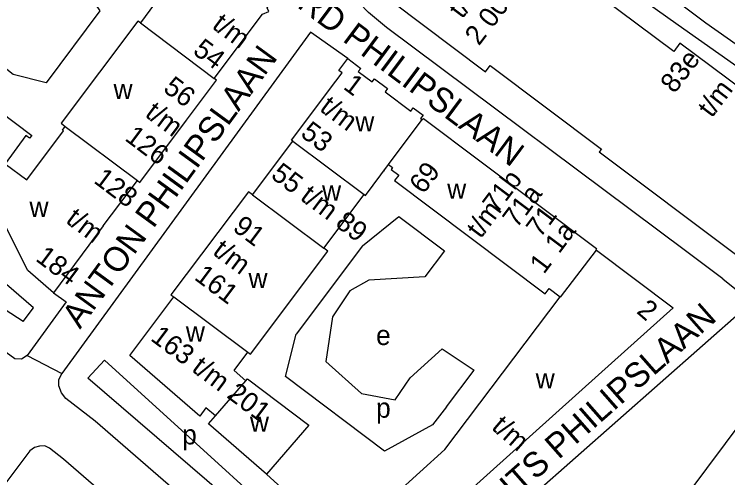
# Model space of a CAD drawing. Extents: x 159261 to 160849, y 382514 to 384534.
# Drawn here: x 160354.6 to 160499.4, y 383689.7 to 383783.7 of the extents above; entities that cross this region are included whole.
import ezdxf

# ---------------------------------------------------------------- set-up
doc = ezdxf.new("R2010")
doc.units = 0
for name, color, linetype in [('BLT_Basislijn', 7, 'Continuous'), ('BLT_Bebouwing', 7, 'Continuous'), ('BLT_Centroide', 7, 'Continuous'), ('BLT_Huisnummer_reeks', 7, 'Continuous'), ('BLT_Huisnummer_zonder_bebouwing', 7, 'Continuous'), ('BLT_Onderverdeling_panden', 7, 'Continuous'), ('BLT_Plantopo', 7, 'Continuous'), ('BLT_Straatnaam', 7, 'Continuous'), ('BLT_Vlakafsluiter', 7, 'Continuous')]:
    doc.layers.add(name, color=color, linetype=linetype)

msp = doc.modelspace()

# ---------------------------------------------------------------- linework, layer by layer
at = {"layer": 'BLT_Basislijn'}
for p, q in [((160490.83, 383735.75), (160430.14, 383781.07)), ((160414.75, 383780.08), (160364.27, 383710.87)), ((160422.31, 383774.74), (160414.75, 383780.08)), ((160425.28, 383736.74), (160411.83, 383718.83)), ((160498.4, 383730.1), (160490.83, 383735.75)), ((160498.4, 383730.1), (160504.24, 383725.34)), ((160452.04, 383679.36), (160504.24, 383725.34)), ((160409.64, 383710.25), (160411.83, 383718.83)), ((160442.32, 383704.12), (160447.92, 383711.55)), ((160429.75, 383695.14), (160409.64, 383710.25)), ((160405.79, 383690.47), (160421.08, 383676.58))]:
    msp.add_line(p, q, dxfattribs=at)
for points in [[(160452.11, 383810.43), (160463.68, 383799.88), (160489.37, 383781.57), (160512.99, 383764.97)], [(160544.3, 383749.08), (160528.34, 383759.05), (160510.47, 383771.01), (160494.97, 383781.94), (160478.14, 383794.64)], [(160430.14, 383781.07), (160426.48, 383784.08), (160424.69, 383785.96), (160423.59, 383788.37)], [(160356.44, 383721.41), (160325.99, 383741.08), (160322.06, 383744.73), (160318.31, 383749.67), (160315.16, 383755.44), (160313.52, 383760.62), (160312.98, 383767.15), (160313.74, 383774.42)], [(160357.23, 383714.5), (160356.07, 383713.77), (160354.74, 383713.87), (160333.91, 383729), (160312.13, 383743.88), (160309.97, 383745.04)], [(160425.28, 383736.74), (160432.69, 383742.73), (160441.94, 383735.73), (160437.95, 383730.45), (160426.59, 383729.78), (160422.7, 383727.62), (160419.17, 383722.34), (160417.83, 383713.29), (160425.11, 383706.82), (160431.92, 383705.5), (160434.96, 383709.97), (160441.48, 383715.86), (160447.92, 383711.55)], [(160356.44, 383721.41), (160358.5, 383724.16), (160351.51, 383730.21)], [(160362.56, 383727.26), (160365.14, 383725.38), (160357.23, 383714.5)], [(160369.56, 383709.91), (160372.9, 383713.59), (160424.43, 383666.77)], [(160422.06, 383664.61), (160418.47, 383660.86), (160417.7, 383660.66), (160416.97, 383660.91), (160410.42, 383667.03), (160371, 383701.19), (160365.08, 383705.81), (160364.23, 383706.97), (160363.68, 383708.34), (160363.68, 383709.56), (160364.27, 383710.87)], [(160422.06, 383664.61), (160421.23, 383665.48), (160369.56, 383709.91)], [(160442.32, 383704.12), (160439.46, 383700.46), (160429.75, 383695.14)], [(160406.32, 383652.42), (160407.01, 383653.62), (160407.25, 383654.84), (160406.99, 383656.12), (160406.32, 383657.17), (160403.73, 383659.59), (160364.64, 383693.46), (160361.79, 383695.69), (160360.82, 383696.18), (160359.71, 383696.14), (160358.73, 383695.85), (160357.8, 383695.17), (160352.3, 383687.91)]]:
    msp.add_lwpolyline(points, dxfattribs=at)
msp.add_lwpolyline([(160343.33, 383806.99), (160355.95, 383800.68), (160367.21, 383791.56), (160371.98, 383784.4), (160361.11, 383769.8), (160354.39, 383771.52), (160352.8, 383772.83), (160335.58, 383799.67)], close=True, dxfattribs=at)
at = {"layer": 'BLT_Bebouwing'}
for p, q in [((160384.23, 383787.44), (160380.2, 383781.98)), ((160402.94, 383747.13), (160411.13, 383758.02)), ((160372.65, 383740.8), (160379.6, 383750.02)), ((160417.43, 383736.28), (160425.65, 383747.18)), ((160472.75, 383735.87), (160488.34, 383724.17)), ((160442.02, 383695.42), (160465.41, 383726.43)), ((160513.51, 383716.32), (160478.99, 383670.1)), ((160421.08, 383676.58), (160442.02, 383695.42))]:
    msp.add_line(p, q, dxfattribs=at)
for points in [[(160395.17, 383770.72), (160404.99, 383783.76), (160406.29, 383784.32), (160405.96, 383785.06), (160406.35, 383785.58), (160400.96, 383789.62), (160401.47, 383790.32), (160399.76, 383791.6), (160399.23, 383790.9), (160393.76, 383795.02), (160394.27, 383795.73), (160392.56, 383797.01), (160392.04, 383796.31), (160391.36, 383796.81)], [(160380.2, 383781.98), (160379.69, 383782.36), (160364.16, 383761.62), (160364.97, 383760.99)], [(160411.13, 383758.02), (160410.9, 383758.2), (160415, 383763.69), (160418.62, 383768.5), (160421.15, 383771.87), (160420.51, 383772.35), (160422.31, 383774.74)], [(160422.31, 383774.74), (160424.92, 383772.75), (160424.43, 383772.1), (160427.22, 383770.01), (160427.7, 383770.66), (160430.37, 383768.66), (160429.9, 383768), (160435.08, 383764.1), (160435.58, 383764.75), (160437.57, 383763.24)], [(160380.1, 383749.63), (160389.58, 383762.26), (160395.64, 383770.34), (160395.17, 383770.72)], [(160345.09, 383768.93), (160358.15, 383759.16), (160357.71, 383758.58), (160356.99, 383759.12), (160352.74, 383753.42), (160357.14, 383750.13), (160364.58, 383760.07), (160364.38, 383760.23), (160364.97, 383760.99)], [(160362.56, 383727.26), (160357.34, 383731.78), (160339.93, 383766.34), (160339.83, 383766.29)], [(160437.57, 383763.24), (160437.08, 383762.6), (160437.41, 383762.37)], [(160437.41, 383762.37), (160437.64, 383762.61), (160472.81, 383736.19), (160472.64, 383735.95), (160472.75, 383735.87)], [(160425.65, 383747.18), (160425.88, 383747), (160430.58, 383753.24)], [(160430.58, 383753.24), (160431.4, 383752.62), (160431.12, 383752.25), (160432.63, 383751.11), (160431.81, 383749.99), (160462.35, 383727.06), (160463.15, 383728.13), (160465.41, 383726.43)], [(160429.69, 383752.08), (160429.58, 383751.93), (160429.54, 383751.96)], [(160379.6, 383750.02), (160380.1, 383749.63)], [(160402.94, 383747.13), (160402.14, 383747.73), (160386.42, 383726.84), (160386.98, 383726.4)], [(160372.65, 383740.8), (160362.56, 383727.26)], [(160401.99, 383715.21), (160402.55, 383714.79), (160418.22, 383735.67), (160417.43, 383736.28)], [(160395.43, 383702.25), (160393.51, 383703.9), (160392.25, 383702.2), (160378.05, 383714.53), (160386.98, 383726.4)], [(160488.34, 383724.17), (160473.21, 383710.61), (160441.83, 383682.45), (160428.3, 383670.3)], [(160401.63, 383709.4), (160399.21, 383711.5), (160401.99, 383715.21)], [(160401.63, 383709.4), (160401.95, 383709.77), (160414.42, 383700.41), (160405.79, 383690.47)], [(160405.79, 383690.47), (160394.04, 383700.66), (160395.43, 383702.25)]]:
    msp.add_lwpolyline(points, dxfattribs=at)
at = {"layer": 'BLT_Onderverdeling_panden'}
for p, q in [((160380.2, 383781.98), (160395.17, 383770.72)), ((160430.58, 383753.24), (160437.41, 383762.37)), ((160364.97, 383760.99), (160379.6, 383750.02)), ((160411.13, 383758.02), (160425.65, 383747.18)), ((160402.94, 383747.13), (160417.43, 383736.28)), ((160386.98, 383726.4), (160401.99, 383715.21)), ((160395.43, 383702.25), (160401.63, 383709.4))]:
    msp.add_line(p, q, dxfattribs=at)
msp.add_lwpolyline([(160465.41, 383726.43), (160465.48, 383726.37), (160472.75, 383735.87)], dxfattribs=at)
at = {"layer": 'BLT_Plantopo'}
msp.add_lwpolyline([(160447.81, 383808.7), (160431.12, 383786.45), (160450.27, 383772.09), (160451.2, 383773.33), (160473.81, 383756.36), (160473.32, 383755.83), (160501.01, 383735.05), (160522.32, 383753.63), (160489.69, 383777.86), (160488.44, 383776.16), (160465.9, 383793.07), (160466.89, 383794.39)], close=True, dxfattribs=at)
at = {"layer": 'BLT_Vlakafsluiter'}
msp.add_line((160357.23, 383714.5), (160364.27, 383710.87), dxfattribs=at)

# ---------------------------------------------------------------- texts
at = {"layer": 'BLT_Centroide'}
for s, p in [('w', (160374.76, 383766.52)), ('w', (160423.83, 383759.99)), ('w', (160417.08, 383745.94)), ('w', (160442.47, 383746.3)), ('w', (160357.7, 383742.62)), ('w', (160402.15, 383728.18)), ('w', (160389.44, 383717.33)), ('e', (160428.04, 383716.64)), ('w', (160460.44, 383707.83)), ('p', (160428.04, 383701.9)), ('w', (160402.44, 383699.04)), ('p', (160388.68, 383696.48))]:
    msp.add_text(s, height=4, dxfattribs=at).set_placement(p)
at = {"layer": 'BLT_Huisnummer_reeks'}
for s, rotation, p in [('t/m', 323.1346, (160394.54, 383781.06)), ('54', 323.1346, (160390.65, 383775.89)), ('56', 323.1346, (160384.63, 383768.25)), ('1', 323.1346, (160421.19, 383768.75)), ('t/m', 323.1346, (160380.93, 383763.14)), ('t/m', 323.1346, (160416.38, 383764.31)), ('53', 323.1346, (160412.5, 383759.12)), ('126', 323.1346, (160376.85, 383758.3)), ('55 t/m 89', 323.1346, (160406.48, 383750.7)), ('69', 53.1346, (160437.66, 383747.08)), ('128', 323.0392, (160370.54, 383749.7)), ('71b', 53.1346, (160452.53, 383743.11)), ('71a', 53.1346, (160456.58, 383740.18)), ('t/m', 323.0392, (160364.84, 383741.61)), ('t/m', 53.1346, (160449.26, 383738.07)), ('71', 53.1346, (160461.37, 383738.23)), ('91', 323.1346, (160398.74, 383740.02)), ('1a', 53.1346, (160465.2, 383735.02)), ('t/m', 323.1346, (160394.66, 383735.19)), ('184', 323.0392, (160358.74, 383733.88)), ('1', 53.1346, (160462.1, 383730.87)), ('161', 323.1346, (160390.95, 383730.07)), ('2', 319.0846, (160480.73, 383723.27)), ('163 t/m 201', 323.1346, (160382.08, 383717.73)), ('t/m', 319.0846, (160451.27, 383699.72))]:
    msp.add_text(s, height=4, rotation=rotation, dxfattribs=at).set_placement(p)
at = {"layer": 'BLT_Huisnummer_zonder_bebouwing'}
for s, p in [('t/m', (160445.52, 383782.64)), ('2 001', (160448.91, 383777.2)), ('83e', (160488.59, 383767.49)), ('t/m', (160496.16, 383762.57))]:
    msp.add_text(s, height=4, rotation=52.6369, dxfattribs=at).set_placement(p)
at = {"layer": 'BLT_Straatnaam'}
for s, rotation, p in [('GERARD PHILIPSLAAN', 323.249, (160396.64, 383796.62)), ('ANTON PHILIPSLAAN', 53.8977, (160367.96, 383719.73)), ('FRITS PHILIPSLAAN', 41.3711, (160449.2, 383679.32))]:
    msp.add_text(s, height=5, rotation=rotation, dxfattribs=at).set_placement(p)

doc.saveas('drawing.dxf')
